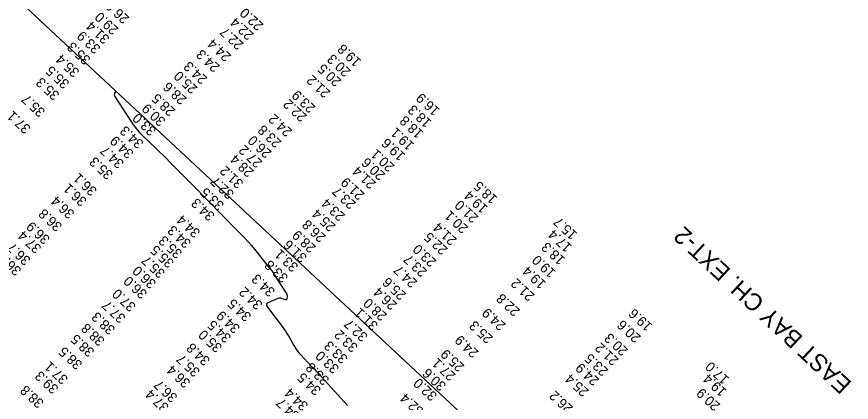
# Model space of a CAD drawing. Extents: x 515576 to 518976, y 1305110 to 1309511.
# Drawn here: x 516788 to 517636, y 1307728 to 1308120 of the extents above; entities that cross this region are included whole.
import ezdxf

# ---------------------------------------------------------------- set-up
doc = ezdxf.new("R2010")
doc.units = 0
for name, color, linetype in [('C-CHAN-TBAS', 7, 'Continuous'), ('V-CHAN-CNTR-IDEN', 7, 'Continuous'), ('V-TOPO-MAJR', 7, 'Continuous'), ('V-TOPO-SOUN', 7, 'Continuous')]:
    doc.layers.add(name, color=color, linetype=linetype)

msp = doc.modelspace()

# ---------------------------------------------------------------- linework, layer by layer
at = {"layer": 'C-CHAN-TBAS'}
msp.add_line((517338.1, 1307624.97), (516401.4, 1308499.6), dxfattribs=at)
at = {"layer": 'V-TOPO-MAJR'}
msp.add_lwpolyline([(516888.93, 1308044.38), (516887.72, 1308042.08), (516887.4, 1308041.26), (516887.32, 1308040.45), (516887.47, 1308039.66), (516887.86, 1308038.87), (516904.23, 1308013.71), (516906.95, 1308009.78), (516909.88, 1308006.03), (516913.02, 1308002.45), (516916.37, 1307999.05), (516930.22, 1307985.78), (516933.66, 1307982.45), (516937.09, 1307979.1), (516940.49, 1307975.72), (516943.86, 1307972.32), (516972.04, 1307943.66), (516977.19, 1307938.44), (516982.33, 1307933.22), (516987.47, 1307927.99), (516992.62, 1307922.77), (517016.59, 1307898.46), (517020, 1307894.92), (517023.31, 1307891.29), (517026.52, 1307887.57), (517029.63, 1307883.77), (517043.64, 1307866.2), (517045.79, 1307863.42), (517047.86, 1307860.59), (517049.85, 1307857.7), (517051.77, 1307854.75), (517062.34, 1307837.96), (517062.62, 1307837.41), (517062.79, 1307836.85), (517062.85, 1307836.26), (517062.81, 1307835.64), (517062.41, 1307833.15), (517062.25, 1307832.63), (517061.96, 1307832.31), (517061.55, 1307832.2), (517061.01, 1307832.3), (517056.86, 1307833.68), (517055.97, 1307833.9), (517055.09, 1307833.95), (517054.21, 1307833.84), (517053.34, 1307833.56), (517044.02, 1307829.72), (517042.56, 1307828.86), (517041.86, 1307827.79), (517041.92, 1307826.51), (517042.74, 1307825.02), (517057.8, 1307805.19), (517059.49, 1307802.89), (517061.09, 1307800.54), (517062.61, 1307798.14), (517064.06, 1307795.69), (517069.67, 1307785.77), (517071.14, 1307783.34), (517072.75, 1307781.02), (517074.5, 1307778.79), (517076.38, 1307776.67), (517087.64, 1307764.74), (517090.17, 1307762.06), (517092.68, 1307759.37), (517095.18, 1307756.66), (517097.67, 1307753.95), (517120.66, 1307728.79), (517124.11, 1307725.04)], dxfattribs=at)

# ---------------------------------------------------------------- texts
at = {"layer": 'V-CHAN-CNTR-IDEN'}
msp.add_text('EAST BAY CH. EXT-2', height=17.52, rotation=136.96281, dxfattribs=at).set_placement((517636.92, 1307748.02))
at = {"layer": 'V-TOPO-SOUN'}
for s, p in [('26.6 ', (516903.28, 1308118.94)), ('22.0 ', (517039.54, 1308111.88)), ('29.0 ', (516892.34, 1308107.71)), ('31.4 ', (516883.42, 1308098.39)), ('22.4 ', (517029.68, 1308102.28)), ('33.9 ', (516874.22, 1308088.5)), ('22.7 ', (517019.38, 1308092.48)), ('24.4 ', (517006.62, 1308080.51)), ('35.3 ', (516864.09, 1308077.34)), ('24.3 ', (516995.22, 1308069.72)), ('19.8 ', (517138.67, 1308075.23)), ('35.4 ', (516852.74, 1308064.61)), ('20.3 ', (517128.16, 1308064.97)), ('35.5 ', (516842.59, 1308052.97)), ('24.3 ', (516982.54, 1308057.57)), ('20.5 ', (517118.59, 1308055.14)), ('25.0 ', (516972.6, 1308047.83)), ('21.2 ', (517107.33, 1308043.6)), ('35.3 ', (516832.53, 1308041.26)), ('28.6 ', (516961.61, 1308036.73)), ('23.9 ', (517092.31, 1308028.3)), ('35.7 ', (516817.99, 1308024.2)), ('28.5 ', (516950.13, 1308024.99)), ('22.2 ', (517083.56, 1308019.33)), ('16.9 ', (517218.48, 1308025.45)), ('30.9 ', (516940.19, 1308014.8)), ('18.3 ', (517210.12, 1308013.38)), ('37.1 ', (516803.26, 1308007.28)), ('33.0 ', (516930.63, 1308005.05)), ('24.2 ', (517068.68, 1308004.18)), ('18.8 ', (517201.84, 1308002.42)), ('34.3 ', (516917.89, 1307992.14)), ('23.8 ', (517057.74, 1307992.91)), ('19.1 ', (517192.55, 1307990.25)), ('34.9 ', (516907.84, 1307981.98)), ('26.0 ', (517047.71, 1307982.42)), ('19.6 ', (517183.42, 1307979.66)), ('34.7 ', (516897.94, 1307971.91)), ('27.2 ', (517038.43, 1307972.55)), ('20.1 ', (517172.48, 1307968.47)), ('35.3 ', (516886.84, 1307960.65)), ('28.4 ', (517029.68, 1307963.09)), ('20.6 ', (517163.15, 1307959.89)), ('31.2 ', (517019.26, 1307951.56)), ('21.4 ', (517153.73, 1307951.12)), ('36.1 ', (516870.5, 1307944.01)), ('36.1 ', (516860.28, 1307933.59)), ('32.7 ', (517009.73, 1307940.84)), ('21.9 ', (517142.15, 1307939.81)), ('18.5 ', (517276.94, 1307935.97)), ('33.5 ', (516999.55, 1307929.32)), ('23.7 ', (517133.38, 1307930.57)), ('19.4 ', (517267.24, 1307926.29)), ('36.4 ', (516847.74, 1307920.78)), ('34.3 ', (516990.18, 1307918.65)), ('23.4 ', (517122.38, 1307918.38)), ('21.0 ', (517257.75, 1307916.65)), ('36.8 ', (516835.19, 1307907.92)), ('34.4 ', (516975.33, 1307901.56)), ('25.4 ', (517112.75, 1307907.73)), ('20.1 ', (517247.34, 1307905.95)), ('36.9 ', (516822.84, 1307894.92)), ('26.8 ', (517102.74, 1307896.86)), ('21.4 ', (517235.71, 1307893.8)), ('15.7 ', (517358, 1307899.6)), ('37.4 ', (516814.18, 1307885.6)), ('34.3 ', (516966.16, 1307890.95)), ('28.9 ', (517092.79, 1307886.16)), ('22.5 ', (517226.59, 1307884.12)), ('17.4 ', (517352.53, 1307886.77)), ('35.3 ', (516957.11, 1307880.51)), ('31.6 ', (517083.75, 1307876.33)), ('36.7 ', (516803.22, 1307873.53)), ('35.5 ', (516948.79, 1307870.88)), ('33.1 ', (517074.88, 1307866.84)), ('23.0 ', (517215.12, 1307871.83)), ('18.3 ', (517345.7, 1307873.97)), ('36.4 ', (516793.84, 1307863.04)), ('35.7 ', (516939.78, 1307860.45)), ('23.7 ', (517205.76, 1307861.67)), ('19.0 ', (517336.23, 1307860.84)), ('36.0 ', (516930.63, 1307849.92)), ('33.8 ', (517064.62, 1307855.76)), ('24.7 ', (517195.69, 1307850.7)), ('19.4 ', (517326.36, 1307849.58)), ('34.3 ', (517051.46, 1307841.66)), ('36.0 ', (516921.54, 1307839.54)), ('25.6 ', (517184.35, 1307838.26)), ('21.2 ', (517314.72, 1307837.2)), ('37.0 ', (516910.04, 1307826.48)), ('34.2 ', (517038.76, 1307828.42)), ('26.4 ', (517175.16, 1307828.16)), ('34.5 ', (517027.24, 1307816.47)), ('28.0 ', (517164.95, 1307817.04)), ('22.8 ', (517299.92, 1307821.78)), ('37.7 ', (516899.67, 1307814.88)), ('31.1 ', (517155.9, 1307807.26)), ('24.9 ', (517285.41, 1307807.22)), ('38.3 ', (516889, 1307803.05)), ('34.9 ', (517015.82, 1307804.38)), ('19.6 ', (517434.26, 1307806.52)), ('38.8 ', (516878.46, 1307791.6)), ('34.5 ', (517006.81, 1307794.77)), ('32.7 ', (517145.4, 1307796.01)), ('25.3 ', (517272.45, 1307794.22)), ('20.6 ', (517422.53, 1307794.91)), ('35.0 ', (516997.56, 1307784.94)), ('33.2 ', (517135.46, 1307785.19)), ('20.3 ', (517409.62, 1307781.58)), ('38.5 ', (516867.92, 1307780.47)), ('33.3 ', (517125.13, 1307773.7)), ('24.9 ', (517257.83, 1307779.57)), ('38.5 ', (516855.67, 1307767.66)), ('34.8 ', (516985.37, 1307771.63)), ('25.9 ', (517243.48, 1307765.34)), ('21.2 ', (517400.13, 1307771.74)), ('35.7 ', (516975.22, 1307760.22)), ('33.0 ', (517116.39, 1307763.57)), ('27.1 ', (517234.61, 1307756.19)), ('23.5 ', (517389.62, 1307760.89)), ('37.1 ', (516841.15, 1307752.7)), ('36.4 ', (516965.41, 1307749.03)), ('33.8 ', (517106.45, 1307751.75)), ('24.9 ', (517380.32, 1307751.28)), ('17.0 ', (517512.17, 1307752.57)), ('39.3 ', (516831.49, 1307743.07)), ('34.5 ', (517098, 1307741.48)), ('30.6 ', (517224.99, 1307745.93)), ('25.4 ', (517369.67, 1307740.14)), ('19.4 ', (517509.75, 1307740.16)), ('36.7 ', (516952.29, 1307734.25)), ('32.0 ', (517215.78, 1307735.8)), ('38.8 ', (516816.61, 1307728.54)), ('37.4 ', (516943.57, 1307724.37)), ('34.4 ', (517084.96, 1307725.8)), ('26.2 ', (517353.73, 1307723.12)), ('20.9 ', (517503.15, 1307725.71)), ('34.7 ', (517076.48, 1307715.8)), ('32.4 ', (517202.19, 1307720.56))]:
    msp.add_text(s, height=9.996, rotation=136.9626, dxfattribs=at).set_placement(p)

doc.saveas('drawing.dxf')
